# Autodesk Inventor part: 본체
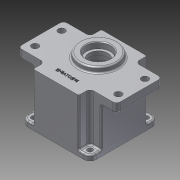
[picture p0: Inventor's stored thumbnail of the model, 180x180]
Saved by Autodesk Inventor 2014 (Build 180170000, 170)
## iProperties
Created: 2015-07
Part Number: 본체
Material: 알루미늄 6061
Document SubType Name: Modeling
Designer: Administrator
Density: 2.71 g/cm^3
Appearance: 알루미늄 - 평지
Mass: 705.361 g
Surface Area: 672.962 cm^2
Volume: 260.281 cm^3
Author: Administrator
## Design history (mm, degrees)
sketch "스케치1"
  geometry: L1 (45, -45)-(-45, -45); L2 (-45, -45)-(-45, 45); L3 (-45, 45)-(45, 45); L4 (45, 45)-(45, -45); L5 (45, -45)-(-45, 45); L6 (-45, -45)-(45, 45); 1 further point
  constraints: 12 end point, 2 midpoint, 2 parallel, 1 horizontal, 1 perpendicular
  dimensions: "d0" = 90 distance of L2.end L3.end; "d1" = 90 distance of L1.end L2.end
extrude "돌출1" new body sketch "스케치1" distance "d2" = 58; taper "d3" = 0 deg
sketch "스케치2"
  geometry: L1 (45, 45)-(-45, 45) reference; L2 (65, -30)-(-65, -30); L3 (-65, -30)-(-65, 30); L4 (-65, 30)-(65, 30); L5 (65, 30)-(65, -30); L6 (65, -30)-(-65, 30); L7 (-65, -30)-(65, 30); L8 (30, -45)-(-30, -45); L9 (-30, -45)-(-30, 45); L10 (-30, 45)-(30, 45); L11 (30, 45)-(30, -45); L12 (30, -45)-(-30, 45); L13 (-30, -45)-(30, 45); 1 further point
  constraints: 24 end point, 4 midpoint, 4 parallel, 2 horizontal, 2 perpendicular, 1 point on line
  dimensions: "d4" = 60 distance between parallel lines of L9 L11; "d5" = 60 distance between parallel lines of L4 L2; "d6" = 130 distance between parallel lines of L3 L5
extrude "돌출2" join sketch "스케치2" distance "d7" = 12; taper "d8" = 0 deg
sketch "스케치3"
  geometry: L1 (30, -30)-(30, -45) reference; L2 (30, -45)-(45, -45) reference; L3 (45, -45)-(45, -30) reference; L4 (45, -30)-(30, -30) reference; L5 (-30, -30)-(-45, -30) reference; L6 (-45, -30)-(-45, -45) reference; L7 (-45, -45)-(-30, -45) reference; L8 (-30, -45)-(-30, -30) reference; L9 (-45, 30)-(-30, 30) reference; L10 (-30, 30)-(-30, 45) reference; L11 (-30, 45)-(-45, 45) reference; L12 (-45, 45)-(-45, 30) reference; L13 (30, 45)-(30, 30) reference; L14 (30, 30)-(45, 30) reference; L15 (45, 30)-(45, 45) reference; L16 (45, 45)-(30, 45) reference; 1 further point
extrude "돌출3" cut sketch "스케치3" distance "d9" = 51; taper "d10" = 0 deg
sketch "스케치4"
  geometry: C1 r 40 at (0, 0); 1 further point
  constraints: 1 centre point, 1 coincident
  dimensions: "d12" = 80 diameter of C1
extrude "돌출4" cut sketch "스케치4" distance "d13" = 9; taper "d14" = 0 deg
sketch "스케치5"
  geometry: C1 r 40 at (0, 0) reference; C2 r 39 at (0, 0)
  constraints: 1 centre point, 1 coincident
  dimensions: "d15" = 78 diameter of C2
extrude "돌출5" cut sketch "스케치5" distance "d16" = 52; taper "d17" = 0 deg
sketch "스케치6"
  geometry: C1 r 39 at (0, 0) reference; C2 r 20.5 at (0, 11); C3 r 14 at (0, -20)
  constraints: 2 centre point, 2 vertical alignment
  dimensions: "d18" = 20.5 radius of C2; "d19" = 14 radius of C3; "d20" = 11 distance of C1.centre C2.centre; "d21" = 20 distance of C3.centre C1.centre
extrude "돌출6" join sketch "스케치6" distance "d22" = 7; taper "d23" = 0 deg
sketch "스케치7"
  geometry: C1 r 17.5 at (0, 11); A1 r 20.5 centre (0, 11) between (7.402, -8.117) and (-7.402, -8.117) reference; 1 further point
  constraints: 1 centre point, 1 coincident
  dimensions: "d25" = 35 diameter of C1
extrude "돌출7" cut sketch "스케치7" distance "d26" = 10; taper "d27" = 0 deg
sketch "스케치8"
  geometry: C1 r 17.5 at (0, 0) reference; C2 r 12.5 at (0, 0); 1 further point
  constraints: 1 centre point, 1 coincident
  dimensions: "d28" = 25 diameter of C2
extrude "돌출8" cut sketch "스케치8" distance "d29" = 5; taper "d30" = 0 deg
sketch "스케치9"
  geometry: C1 r 11 at (0, -20); A1 r 14 centre (0, -20) between (-7.402, -8.117) and (7.402, -8.117) reference; 1 further point
  constraints: 1 centre point, 1 coincident
  dimensions: "d31" = 22 diameter of C1
extrude "돌출9" cut sketch "스케치9" distance "d32" = 7; taper "d33" = 0 deg
sketch "스케치10"
  geometry: C1 r 11 at (0, 0) reference; C2 r 9.5 at (0, 0); 1 further point
  constraints: 1 centre point, 1 coincident
  dimensions: "d34" = 19 diameter of C2
extrude "돌출10" cut sketch "스케치10" distance "d35" = 1; taper "d36" = 0 deg
sketch "스케치11"
  geometry: C1 r 12.5 at (0, 11) reference; C2 r 25 at (0, 11); 1 further point
  constraints: 1 centre point, 1 coincident
  dimensions: "d37" = 50 diameter of C2
extrude "돌출11" join sketch "스케치11" distance "d38" = 7; taper "d39" = 0 deg
sketch "스케치12"
  geometry: C1 r 25 at (0, 0) reference; C2 r 16 at (0, 0); 1 further point
  constraints: 1 centre point, 1 coincident
  dimensions: "d40" = 32 diameter of C2
extrude "돌출12" cut sketch "스케치12" distance "d41" = 8; taper "d42" = 0 deg
sketch "스케치13"
  geometry: L1 (-24.749, -24.749)-(0, 0); L2 (0, 0)-(-35, 0); C1 r 40 at (0, 0) reference; A1 r 39 centre (0, 0) between (-21.134, -32.777) and (-32.777, -21.134) reference; A2 r 35 centre (0, 0) between (-24.749, -24.749) and (-35, 0); A3 r 4 centre (-24.749, -24.749) between (-21.809, -27.462) and (-27.462, -21.809); A4 r 3.5 centre (-29.836, -19.238) between (-32.777, -21.134) and (-27.412, -21.762); A5 r 3.5 centre (-19.238, -29.836) between (-21.762, -27.412) and (-21.134, -32.777)
  constraints: 14 point on circle, 4 centre point, 4 end point, 4 tangent, 1 coincident, 1 horizontal
  dimensions: "d43" = 35 radius of A2; "d44" = 4 radius of A3; "d45" = 45 deg angle of L1 L2; "d46" = 3.5 radius of A4; "d47" = 3.5 radius of A5
extrude "돌출13" join sketch "스케치13" stored distance "d48" = 8; taper "d49" = 0 deg
sketch "스케치14"
  geometry: A1 r 4 centre (-24.749, -24.749) between (-21.809, -27.462) and (-27.462, -21.809) reference; 1 further point
  constraints: 1 coincident
hole "구멍1" sketch "스케치14" at (-24.749, -24.749) diameter "d50" = 3.459; stored, may be unused: countersink angle "d54" = 90 deg, drill point angle "d56" = 118 deg; dims "d51" = 12, "d52" = 4, "d53" = 2, "d55" = 15
fillet "모깎기1" dims "d60" = 8
sketch "스케치15"
  geometry: L1 (-45, -37)-(-45, 37) reference; L2 (-37, 45)-(37, 45) reference; L3 (45, 37)-(45, -37) reference; L4 (37, -45)-(-37, -45) reference; C1 r 40 at (0, 0) reference; C2 r 3.5 at (-37, 37); C3 r 3.5 at (37, 37); C4 r 3.5 at (37, -37); C5 r 3.5 at (-37, -37); A1 r 8 centre (-37, -37) between (-45, -37) and (-37, -45) reference; A2 r 8 centre (-37, 37) between (-37, 45) and (-45, 37) reference; A3 r 8 centre (37, 37) between (45, 37) and (37, 45) reference; A4 r 8 centre (37, -37) between (37, -45) and (45, -37) reference; 1 further point
  constraints: 4 centre point, 4 coincident
  dimensions: "d61" = 7 diameter of C2; "d62" = 7 diameter of C3; "d63" = 7 diameter of C4; "d64" = 7 diameter of C5
extrude "돌출14" cut sketch "스케치15" stored distance "d65" = 8; taper "d66" = 0 deg
fillet "모깎기2" dims "d67" = 5
sketch "스케치16"
  geometry: C1 r 4.5 at (-55, 17.5); C2 r 4.5 at (55, 17.5); C3 r 4.5 at (55, -17.5); C4 r 4.5 at (-55, -17.5); 1 further point
  constraints: 4 centre point, 2 horizontal alignment, 2 vertical alignment
  dimensions: "d68" = 9 diameter of C1; "d69" = 9 diameter of C2; "d70" = 9 diameter of C3; "d71" = 9 diameter of C4; "d72" = 110 distance of C2.centre C1.centre; "d73" = 35 distance of C2.centre C3.centre; "d74" = 55 horizontal distance of point (0, 0) C2.centre; "d75" = 17.5 vertical distance of point (0, 0) C3.centre
extrude "돌출15" cut sketch "스케치16" stored distance "d76" = 8; taper "d77" = 0 deg
sketch "스케치17"
  geometry: L1 (-30, -45)-(30, -45) reference; 2 further points
  constraints: 1 vertical alignment, 1 other
  dimensions: "d78" = 15 distance from line of L1 point (0, -30)
feature "엠보싱1" sketch "스케치17" dims "d6" = 130, "d79" = 0.5, "d80" = 0
fillet "모깎기3" dims "d81" = 5
fillet "모깎기4" dims "d82" = 3
fillet "모깎기5" dims "d83" = 2
fillet "모깎기6" dims "d84" = 2
fillet "모깎기7" dims "d85" = 2
fillet "모깎기8" dims "d86" = 2
fillet "모깎기9" dims "d87" = 2
fillet "모깎기10" dims "d88" = 2
fillet "모깎기11" dims "d89" = 2
fillet "모깎기12" dims "d90" = 0.3
chamfer "모따기1" distance "d91" = 1; stored, may be unused: second distance "d92" = 2, angle "d93" = 45 deg
node "솔리드1"
pattern_circular "원형 패턴1" dims angle "d58" = 360 deg
node "투영된 루프1"
node "투영된 루프2"
node "투영된 루프3"
node "투영된 루프4"
node "투영된 루프5"
